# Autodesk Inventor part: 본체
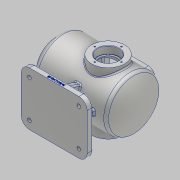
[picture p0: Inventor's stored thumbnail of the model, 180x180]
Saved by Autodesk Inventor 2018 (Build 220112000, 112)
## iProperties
Created: 2021-11
Part Number: 본체
Material: 알루미늄 6061
Document SubType Name: Modeling
Designer: home
Density: 2.7 g/cm^3
Appearance: 알루미늄 - 평지
Mass: 3539.14 g
Surface Area: 2407.21 cm^2
Volume: 1310.79 cm^3
Author: home
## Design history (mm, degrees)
sketch "스케치1"
  geometry: L1 (80, 65)-(-80, 65); L2 (-80, 65)-(-80, -65); L3 (-80, -65)-(80, -65); L4 (80, -65)-(80, 65); L5 (80, 65)-(-80, -65); L6 (-80, 65)-(80, -65); 1 further point
  constraints: 12 end point, 2 midpoint, 2 parallel, 1 horizontal, 1 perpendicular
  dimensions: "d0" = 160 distance of L2.end L3.end; "d1" = 130 distance of L1.end L2.end
extrude "돌출1" new body sketch "스케치1" distance "d2" = 14; taper "d3" = 0 deg
fillet "모깎기1" dims "d4" = 20
sketch "스케치2"
  geometry: L1 (-103.289, 114)-(100, 114); L2 (60, 0)-(-60, 0) reference; L3 (-110, 146.5)-(-85, 146.5); L4 (-85, 146.5)-(-85, 169); L5 (-85, 169)-(71.239, 169); L6 (-110, 146.5)-(-110, 161.5); L7 (-110, 161.5)-(-100, 161.5); L8 (-100, 161.5)-(-100, 179); L9 (-100, 179)-(75.993, 179); L10 (-80, 0)-(-80, 14) reference; A1 r 100 centre (0, 114) between (100, 114) and (75.993, 179); A2 r 90 centre (0, 114) between (90, 114) and (71.239, 169); 1 further point
  constraints: 16 end point, 5 perpendicular, 4 point on circle, 2 centre point, 2 horizontal, 1 point on line, 1 vertical
  dimensions: "d5" = 114 distance between parallel lines of L2 L1; "d6" = 65 diameter of L3 L1; "d7" = 95 diameter of L7 L1; "d8" = 110 diameter of L5 L1; "d9" = 130 diameter of L9 L1; "d15" = 10 radial gap between concentric circles of A1 A2; "d16" = 10 distance of L6.end L7.end; "d17" = 100 radius of A1; "d18" = 25 distance of L3.start L3.end; "d20" = 110 distance from line of L6 A1.centre; "d22" = 30 distance between parallel lines of L10 L6; "d23" = 55 distance from line of L5 A1.centre
revolve "회전1" sketch "스케치2" stored, may be unused: angle "d24" = 90 deg
sketch "스케치3"
  geometry: L1 (60, 14)-(-60, 14) reference; L2 (-60, 14)-(-45.352, 54.246); L3 (60, 14)-(45.352, 54.246); L4 (-100, 49)-(75.993, 49) reference; L5 (-60, 14)-(60, 14); L6 (-80, 14)-(-60, 14) reference; L7 (60, 14)-(80, 14) reference; L8 (-45.352, 54.246)-(45.352, 54.246); L9 (71.239, 59)-(-85, 59) reference; 2 further points
  constraints: 8 end point, 2 point on line, 1 collinear, 1 parallel, 1 vertical alignment
  dimensions: "d25" = 120 distance of L3.start L2.start; "d26" = 110 deg angle of L6 L2; "d27" = 110 deg angle of L7 L3; "d28" = 90.70367 distance of L2.end L3.end; "d29" = 61.16984 distance from line of L2 point (0, 0)
extrude "돌출2" join sketch "스케치3" stored distance "d30" = 14; taper "d31" = 0 deg
sketch "스케치4"
  geometry: L1 (14, -45)-(14, -65) reference; L2 (14, -50)-(58.485, -33.809); 2 further points
  constraints: 2 end point, 1 point on line, 2 other
  dimensions: "d32" = 50 vertical distance of point (0, 0) L2.start; "d33" = 110 deg angle of L1 L2
feature "리브1" sketch "스케치4" dims "d34" = 1, "d35" = 14, "d36" = 0, "d37" = 0, "d38" = 1, "d39" = 1
node "작업 평면1"
node "작업 평면2"
sketch "스케치8"
  geometry: L1 (60, 30)-(-60, 30); L2 (-60, 30)-(-60, -30); L3 (-60, -30)-(60, -30); L4 (60, -30)-(60, 30); L5 (110, 47.5)-(110, -47.5) reference; L6 (60, 0)-(-60, 0); 2 further points
  constraints: 10 end point, 3 midpoint, 2 parallel, 1 coincident, 1 horizontal, 1 perpendicular
  dimensions: "d53" = 50 distance between parallel lines of L4 L5; "d54" = 120 distance between parallel lines of L2 L4; "d55" = 60 distance between parallel lines of L1 L3
extrude "돌출5" join sketch "스케치8" stored distance "d56" = 18; taper "d57" = 0 deg
sketch "스케치9"
  geometry: L1 (-50, -20)-(50, -20); L2 (50, -20)-(50, 20); L3 (50, 20)-(-50, 20); L4 (-50, 20)-(-50, -20); L5 (-50, 0)-(50, 0); L6 (-60, 30)-(-60, -30) reference; L7 (60, -30)-(60, 30) reference; L8 (60, 30)-(-60, 30) reference; L9 (-60, -30)-(60, -30) reference; 1 further point
  constraints: 10 end point, 2 midpoint, 2 parallel, 1 horizontal, 1 perpendicular
  dimensions: "d58" = 10 distance between parallel lines of L6 L4; "d59" = 10 distance between parallel lines of L7 L2; "d60" = 10 distance between parallel lines of L8 L3; "d61" = 10 distance between parallel lines of L9 L1
extrude "돌출6" cut sketch "스케치9" stored distance "d62" = 18; taper "d63" = 0 deg
fillet "모깎기2" dims "d64" = 15
fillet "모깎기3" dims "d65" = 5
fillet "모깎기4" dims "d66" = 10
fillet "모깎기5" dims "d67" = 3
fillet "모깎기6" dims "d68" = 3
fillet "모깎기7" dims "d69" = 3
chamfer "모따기1" distance "d70" = 1; stored, may be unused: second distance "d71" = 2, angle "d72" = 45 deg
fillet "모깎기9" dims "d74" = 3
sketch "스케치10"
  geometry: L1 (60, 65)-(-60, 65) reference; L2 (80, -45)-(80, 45) reference; L3 (-60, -65)-(60, -65) reference; L4 (-80, 45)-(-80, -45) reference; A1 r 20 centre (60, 45) between (80, 45) and (60, 65) reference; A2 r 20 centre (60, 45) between (80, 45) and (60, 65) reference; A3 r 20 centre (60, -45) between (60, -65) and (80, -45) reference; A4 r 20 centre (-60, -45) between (-80, -45) and (-60, -65) reference; A5 r 20 centre (-60, 45) between (-60, 65) and (-80, 45) reference; 1 further point
hole "구멍1" sketch "스케치10" at (-60, 45), (-60, -45), (60, 45), (60, -45) diameter "d75" = 9; stored, may be unused: countersink angle "d79" = 90 deg, drill point angle "d81" = 0 deg; dims "d76" = 6, "d77" = 18, "d78" = 2, "d80" = 8
sketch "스케치11"
  geometry: C1 r 47.5 at (0, 0) reference; 2 further points
  constraints: 1 vertical alignment
  dimensions: "d82" = 40 distance of C1.centre point (0, 40)
hole "구멍2" sketch "스케치11" at (0, 40) diameter "d83" = 3.459; stored, may be unused: countersink angle "d87" = 90 deg, drill point angle "d89" = 118 deg; dims "d84" = 11, "d85" = 18, "d86" = 2, "d88" = 13
sketch "스케치13"
  geometry: L1 (50, 15)-(50, -15) reference; L2 (45, -20)-(-45, -20) reference; L3 (-50, -15)-(-50, 15) reference; L4 (-45, 20)-(45, 20) reference; L5 (45, 30)-(-45, 30) reference; L6 (-60, 15)-(-60, -15) reference; L7 (-45, -30)-(45, -30) reference; L8 (60, -15)-(60, 15) reference; A1 r 5 centre (45, -15) between (45, -20) and (50, -15) reference; A2 r 5 centre (-45, -15) between (-50, -15) and (-45, -20) reference; A3 r 5 centre (-45, 15) between (-45, 20) and (-50, 15) reference; A4 r 5 centre (45, 15) between (50, 15) and (45, 20) reference; A5 r 15 centre (45, 15) between (60, 15) and (45, 30) reference; A6 r 15 centre (-45, 15) between (-45, 30) and (-60, 15) reference; A7 r 15 centre (-45, -15) between (-60, -15) and (-45, -30) reference; A8 r 15 centre (45, -15) between (45, -30) and (60, -15) reference; 6 further points
  constraints: 2 horizontal alignment, 2 vertical alignment, 1 midpoint
  dimensions: "d104" = 55 distance of point (0, 0) point (-55, 0); "d105" = 55 distance of point (0, 0) point (55, 0); "d106" = 50 distance of point (0, -25) point (0, 25); "d107" = 25 distance of point (0, 0) point (0, 25)
hole "구멍4" sketch "스케치13" at (0, 25), (0, -25), (-55, 0), (55, 0) diameter "d108" = 3.459; stored, may be unused: countersink angle "d112" = 90 deg, drill point angle "d114" = 118 deg; dims "d109" = 9, "d110" = 18, "d111" = 2, "d113" = 11
node "작업 평면3"
sketch "스케치14"
  geometry: L1 (-45.822, 8.766)-(45.822, 8.766); L2 (45.822, 8.766)-(45.822, 1.234); L3 (45.822, 1.234)-(-45.822, 1.234); L4 (-45.822, 1.234)-(-45.822, 8.766); L5 (-45.822, 5)-(45.822, 5); L6 (0, 8.766)-(0, 1.234); L7 (-60, 0)-(60, 0) reference; 2 further points
  constraints: 5 midpoint, 4 end point, 1 vertical alignment, 2 other
  dimensions: "d147" = 5 distance between parallel lines of L7 L5
feature "엠보싱1" sketch "스케치14" dims "d5" = 114, "d6" = 65, "d7" = 95, "d8" = 110, "d9" = 130, "d15" = 10, "d16" = 10, "d17" = 100, "d18" = 25, "d20" = 110, "d22" = 30, "d23" = 55, "d116" = 0.5, "d117" = 0
node "작업 평면4"
sketch "스케치15"
  geometry: L1 (-110, 66.5)-(-110, 161.5) reference; C1 r 40 at (17, 114); 2 further points
  constraints: 1 centre point, 1 horizontal alignment, 1 midpoint
  dimensions: "d121" = 127 distance from line of L1 C1.centre; "d122" = 80 diameter of C1
extrude "돌출7" join sketch "스케치15" stored distance "d123" = 40; taper "d124" = 0 deg
sketch "스케치16"
  geometry: C1 r 40 at (0, 0) reference; C2 r 26 at (0, 0); 1 further point
  constraints: 1 centre point, 1 coincident
  dimensions: "d125" = 52 diameter of C2
extrude "돌출8" cut sketch "스케치16" distance "d126" = 18; taper "d127" = 0 deg
sketch "스케치17"
  geometry: C1 r 26 at (0, 0) reference; C2 r 21 at (0, 0); 1 further point
  constraints: 1 centre point, 1 coincident
  dimensions: "d128" = 42 diameter of C2
extrude "돌출9" cut sketch "스케치17" stored distance "d129" = 18; taper "d130" = 0 deg
sketch "스케치18"
  geometry: C1 r 40 at (0, 0) reference; 2 further points
  constraints: 1 vertical alignment
  dimensions: "d131" = 32.5 distance of C1.centre point (0, 32.5)
hole "구멍5" sketch "스케치18" at (0, 32.5) diameter "d132" = 3.459; stored, may be unused: countersink angle "d136" = 90 deg, drill point angle "d138" = 118 deg; dims "d133" = 11, "d134" = 18, "d135" = 2, "d137" = 13
fillet "모깎기10" dims "d142" = 3
chamfer "모따기2" distance "d143" = 1; stored, may be unused: second distance "d144" = 2, angle "d145" = 45 deg
fillet "모깎기11" dims "d146" = 0.3
node "솔리드1"
mirror "미러1"
pattern_circular "원형 패턴1" dims angle "d91" = 360 deg
pattern_circular "원형 패턴3" dims angle "d140" = 360 deg
mirror "미러5"
node "투영된 루프1"
node "투영된 루프2"
other parameters: "d40" = -127, "d52" = 184, "d115" = 126.25, "d120" = 75
